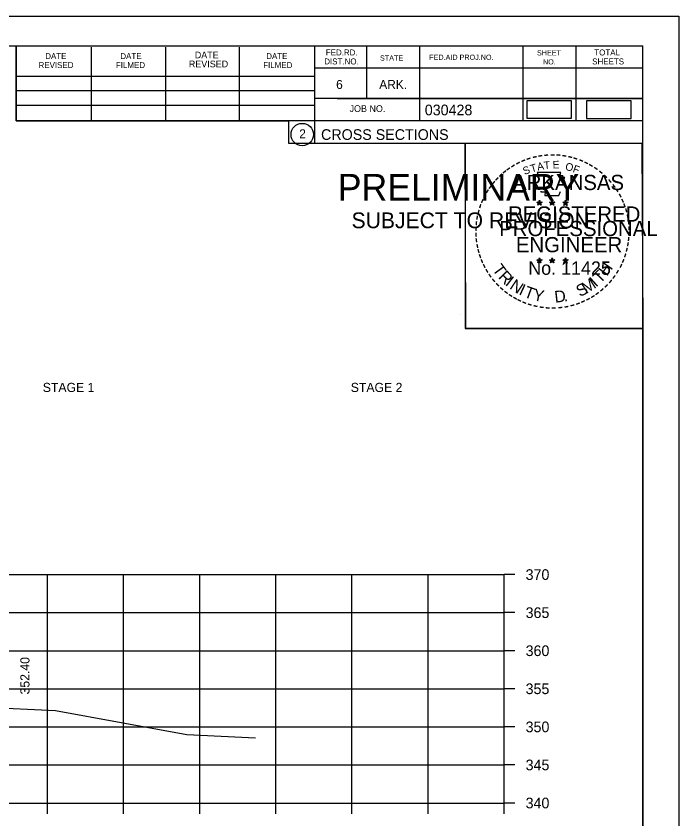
# Model space of a CAD drawing. Extents: x 1374859 to 1376773, y 382242 to 389804.
# Drawn here: x 1376210.5 to 1376297.5, y 382563 to 382668.4 of the extents above; entities that cross this region are included whole.
import ezdxf

# ---------------------------------------------------------------- set-up
doc = ezdxf.new("R2010")
doc.units = 0
for name, color, linetype in [('R_Axis', 7, 'Continuous'), ('R_Axis Annot', 7, 'Continuous'), ('R_Border', 7, 'Continuous'), ('R_Border PE', 7, 'Continuous'), ('R_Border Prem', 7, 'Continuous'), ('R_Exist Surface', 7, 'Continuous'), ('R_Grid', 7, 'Continuous'), ('R_MOT', 7, 'Continuous'), ('R_No Plot', 7, 'Continuous'), ('R_Xsect Elev', 7, 'Continuous')]:
    doc.layers.add(name, color=color, linetype=linetype)

msp = doc.modelspace()

# ---------------------------------------------------------------- linework, layer by layer
at = {"layer": 'R_Axis'}
for p, q in [((1376274.57, 382565.06), (1376274.57, 382595.06)), ((1376275.97, 382595.06), (1376274.57, 382595.06)), ((1376275.97, 382590.06), (1376274.57, 382590.06)), ((1376275.97, 382585.06), (1376274.57, 382585.06)), ((1376275.97, 382580.06), (1376274.57, 382580.06)), ((1376275.97, 382575.06), (1376274.57, 382575.06)), ((1376275.97, 382570.06), (1376274.57, 382570.06)), ((1375994.57, 382565.06), (1376274.57, 382565.06)), ((1376214.57, 382563.66), (1376214.57, 382565.06)), ((1376224.57, 382563.66), (1376224.57, 382565.06)), ((1376234.57, 382563.66), (1376234.57, 382565.06)), ((1376244.57, 382563.66), (1376244.57, 382565.06)), ((1376254.57, 382563.66), (1376254.57, 382565.06)), ((1376264.57, 382563.66), (1376264.57, 382565.06)), ((1376274.57, 382563.66), (1376274.57, 382565.06)), ((1376275.97, 382565.06), (1376274.57, 382565.06))]:
    msp.add_line(p, q, dxfattribs=at)
at = {"layer": 'R_Border'}
for p, q in [((1375976.57, 382664.52), (1376292.75, 382664.52)), ((1376210.49, 382654.64), (1376210.49, 382664.52)), ((1376249.65, 382664.52), (1376249.65, 382651.72)), ((1376256.49, 382664.52), (1376256.49, 382657.58)), ((1376263.43, 382664.52), (1376263.43, 382654.64)), ((1376277.01, 382664.52), (1376277.01, 382654.64)), ((1376283.95, 382664.52), (1376283.95, 382654.64)), ((1376292.75, 382459.06), (1376292.75, 382664.52)), ((1376220.35, 382654.64), (1376220.35, 382664.32)), ((1376230.11, 382654.64), (1376230.11, 382664.32)), ((1376239.79, 382654.64), (1376239.79, 382664.32)), ((1376292.75, 382661.58), (1376249.65, 382661.58)), ((1376292.75, 382661.6), (1376292.75, 382661.6)), ((1376210.49, 382660.5), (1376249.65, 382660.5)), ((1376210.49, 382658.64), (1376249.65, 382658.64)), ((1376292.75, 382657.58), (1376249.65, 382657.58)), ((1376252.61, 382657.58), (1376292.75, 382657.58)), ((1376210.49, 382654.64), (1376210.49, 382656.7)), ((1376210.49, 382656.7), (1376249.65, 382656.7)), ((1376292.75, 382654.64), (1376210.49, 382654.64)), ((1376249.65, 382651.72), (1376292.75, 382651.72))]:
    msp.add_line(p, q, dxfattribs=at)
msp.add_circle((1376248.04, 382652.85), 1.47, dxfattribs=at)
at = {"layer": 'R_Border PE'}
for p, q in [((1376278.84, 382643.97), (1376279.18, 382643.86)), ((1376278.84, 382643.97), (1376279.09, 382643.93)), ((1376278.84, 382643.97), (1376279.07, 382643.85)), ((1376278.97, 382643.57), (1376279.18, 382643.86)), ((1376278.97, 382643.57), (1376279.09, 382643.81)), ((1376278.97, 382643.57), (1376279.18, 382643.78)), ((1376279.18, 382644.23), (1376279.14, 382643.98)), ((1376279.18, 382643.86), (1376279.18, 382644.23)), ((1376279.18, 382644.23), (1376279.23, 382643.98)), ((1376279.53, 382643.97), (1376279.18, 382643.86)), ((1376279.4, 382643.57), (1376279.18, 382643.86)), ((1376279.4, 382643.57), (1376279.18, 382643.78)), ((1376279.53, 382643.97), (1376279.25, 382643.92)), ((1376279.4, 382643.57), (1376279.26, 382643.86)), ((1376279.53, 382643.97), (1376279.33, 382643.87)), ((1376280.51, 382643.97), (1376280.85, 382643.86)), ((1376280.51, 382643.97), (1376280.76, 382643.93)), ((1376280.51, 382643.97), (1376280.74, 382643.85)), ((1376280.64, 382643.57), (1376280.85, 382643.86)), ((1376280.64, 382643.57), (1376280.76, 382643.81)), ((1376280.64, 382643.57), (1376280.85, 382643.78)), ((1376280.85, 382644.23), (1376280.81, 382643.98)), ((1376280.85, 382643.86), (1376280.85, 382644.23)), ((1376280.85, 382644.23), (1376280.9, 382643.98)), ((1376281.2, 382643.97), (1376280.85, 382643.86)), ((1376281.07, 382643.57), (1376280.85, 382643.86)), ((1376281.07, 382643.57), (1376280.85, 382643.78)), ((1376281.2, 382643.97), (1376280.92, 382643.92)), ((1376281.07, 382643.57), (1376280.93, 382643.86)), ((1376281.2, 382643.97), (1376281, 382643.87)), ((1376282.27, 382643.96), (1376282.62, 382643.85)), ((1376282.27, 382643.96), (1376282.52, 382643.92)), ((1376282.27, 382643.96), (1376282.51, 382643.84)), ((1376282.4, 382643.55), (1376282.62, 382643.85)), ((1376282.4, 382643.55), (1376282.53, 382643.8)), ((1376282.4, 382643.55), (1376282.62, 382643.77)), ((1376282.62, 382644.22), (1376282.58, 382643.96)), ((1376282.62, 382643.85), (1376282.62, 382644.22)), ((1376282.62, 382644.22), (1376282.67, 382643.97)), ((1376282.97, 382643.96), (1376282.62, 382643.85)), ((1376282.83, 382643.55), (1376282.62, 382643.85)), ((1376282.83, 382643.55), (1376282.62, 382643.77)), ((1376282.97, 382643.96), (1376282.68, 382643.91)), ((1376282.83, 382643.55), (1376282.69, 382643.84)), ((1376282.97, 382643.96), (1376282.76, 382643.86)), ((1376278.83, 382636.4), (1376279.18, 382636.29)), ((1376278.83, 382636.4), (1376279.08, 382636.36)), ((1376278.83, 382636.4), (1376279.07, 382636.28)), ((1376278.96, 382635.99), (1376279.18, 382636.29)), ((1376278.96, 382635.99), (1376279.09, 382636.24)), ((1376278.96, 382635.99), (1376279.18, 382636.21)), ((1376279.18, 382636.65), (1376279.14, 382636.4)), ((1376279.18, 382636.29), (1376279.18, 382636.65)), ((1376279.18, 382636.65), (1376279.23, 382636.4)), ((1376279.53, 382636.4), (1376279.18, 382636.29)), ((1376279.39, 382635.99), (1376279.18, 382636.29)), ((1376279.39, 382635.99), (1376279.18, 382636.21)), ((1376279.53, 382636.4), (1376279.24, 382636.35)), ((1376279.39, 382635.99), (1376279.26, 382636.28)), ((1376279.53, 382636.4), (1376279.32, 382636.3)), ((1376280.5, 382636.4), (1376280.85, 382636.29)), ((1376280.5, 382636.4), (1376280.75, 382636.36)), ((1376280.5, 382636.4), (1376280.74, 382636.28)), ((1376280.63, 382635.99), (1376280.85, 382636.29)), ((1376280.63, 382635.99), (1376280.76, 382636.24)), ((1376280.63, 382635.99), (1376280.85, 382636.21)), ((1376280.85, 382636.65), (1376280.81, 382636.4)), ((1376280.85, 382636.29), (1376280.85, 382636.65)), ((1376280.85, 382636.65), (1376280.9, 382636.4)), ((1376281.2, 382636.4), (1376280.85, 382636.29)), ((1376281.06, 382635.99), (1376280.85, 382636.29)), ((1376281.06, 382635.99), (1376280.85, 382636.21)), ((1376281.2, 382636.4), (1376280.91, 382636.35)), ((1376281.06, 382635.99), (1376280.93, 382636.28)), ((1376281.2, 382636.4), (1376280.99, 382636.3)), ((1376282.27, 382636.39), (1376282.62, 382636.28)), ((1376282.27, 382636.39), (1376282.52, 382636.35)), ((1376282.27, 382636.39), (1376282.5, 382636.27)), ((1376282.4, 382635.98), (1376282.62, 382636.28)), ((1376282.4, 382635.98), (1376282.53, 382636.23)), ((1376282.4, 382635.98), (1376282.61, 382636.2)), ((1376282.62, 382636.64), (1376282.58, 382636.39)), ((1376282.83, 382635.98), (1376282.61, 382636.2)), ((1376282.62, 382636.28), (1376282.62, 382636.64)), ((1376282.62, 382636.64), (1376282.67, 382636.39)), ((1376282.96, 382636.39), (1376282.62, 382636.28)), ((1376282.83, 382635.98), (1376282.62, 382636.28)), ((1376282.96, 382636.39), (1376282.68, 382636.34)), ((1376282.83, 382635.98), (1376282.69, 382636.27)), ((1376282.96, 382636.39), (1376282.76, 382636.29))]:
    msp.add_line(p, q, dxfattribs=at)
for points in [[(1376278.88, 382647.85), (1376279.15, 382647.02)], [(1376282.39, 382646.93), (1376282.53, 382647.21), (1376281.84, 382647.19), (1376281.99, 382647.85), (1376278.88, 382647.85)], [(1376279.37, 382645.43), (1376279.37, 382645.34), (1376279.93, 382645.32), (1376279.88, 382644.85), (1376281.75, 382644.85), (1376281.95, 382645.39)], [(1376279.18, 382644.23), (1376279.4, 382643.57), (1376278.84, 382643.97), (1376279.53, 382643.97), (1376278.97, 382643.57), (1376279.18, 382644.23)], [(1376280.85, 382644.23), (1376281.07, 382643.57), (1376280.51, 382643.97), (1376281.2, 382643.97), (1376280.64, 382643.57), (1376280.85, 382644.23)], [(1376282.62, 382644.22), (1376282.83, 382643.55), (1376282.27, 382643.96), (1376282.97, 382643.96), (1376282.4, 382643.55), (1376282.62, 382644.22)], [(1376279.18, 382636.65), (1376279.39, 382635.99), (1376278.83, 382636.4), (1376279.53, 382636.4), (1376278.96, 382635.99), (1376279.18, 382636.65)], [(1376280.85, 382636.65), (1376281.06, 382635.99), (1376280.5, 382636.4), (1376281.2, 382636.4), (1376280.63, 382635.99), (1376280.85, 382636.65)], [(1376282.62, 382636.64), (1376282.83, 382635.98), (1376282.27, 382636.39), (1376282.96, 382636.39), (1376282.4, 382635.98), (1376282.62, 382636.64)]]:
    msp.add_lwpolyline(points, dxfattribs=at)
for centre, radius in [((1376279.18, 382643.86), 0.172), ((1376279.18, 382643.86), 0.145), ((1376279.18, 382643.86), 0.116), ((1376279.18, 382643.86), 0.0991), ((1376279.18, 382643.86), 0.0747), ((1376279.18, 382643.86), 0.0495), ((1376279.18, 382643.86), 0.0296), ((1376280.85, 382643.86), 0.172), ((1376280.85, 382643.86), 0.145), ((1376280.85, 382643.86), 0.116), ((1376280.85, 382643.86), 0.0991), ((1376280.85, 382643.86), 0.0747), ((1376280.85, 382643.86), 0.0495), ((1376280.85, 382643.86), 0.0296), ((1376282.62, 382643.85), 0.172), ((1376282.62, 382643.85), 0.145), ((1376282.62, 382643.85), 0.116), ((1376282.62, 382643.85), 0.0991), ((1376282.62, 382643.85), 0.0747), ((1376282.62, 382643.85), 0.0495), ((1376282.62, 382643.85), 0.0296), ((1376279.18, 382636.29), 0.172), ((1376279.18, 382636.29), 0.145), ((1376279.18, 382636.29), 0.116), ((1376279.18, 382636.29), 0.0991), ((1376279.18, 382636.29), 0.0747), ((1376279.18, 382636.29), 0.0495), ((1376279.18, 382636.29), 0.0296), ((1376280.85, 382636.29), 0.172), ((1376280.85, 382636.29), 0.145), ((1376280.85, 382636.29), 0.116), ((1376280.85, 382636.29), 0.0991), ((1376280.85, 382636.29), 0.0747), ((1376280.85, 382636.29), 0.0495), ((1376280.85, 382636.29), 0.0296), ((1376282.62, 382636.28), 0.172), ((1376282.62, 382636.28), 0.145), ((1376282.62, 382636.28), 0.116), ((1376282.62, 382636.28), 0.0991), ((1376282.62, 382636.28), 0.0747), ((1376282.62, 382636.28), 0.0495), ((1376282.62, 382636.28), 0.0296)]:
    msp.add_circle(centre, radius, dxfattribs=at)
at = {"layer": 'R_Exist Surface'}
msp.add_lwpolyline([(1376060.43, 382576.48), (1376068.34, 382576.55), (1376071, 382576.59), (1376082.43, 382577.26), (1376101.6, 382577.35), (1376109.94, 382581.24), (1376116.08, 382584.23), (1376119.45, 382584.36), (1376124.3, 382584.58), (1376129.36, 382584.71), (1376136.25, 382584.9), (1376143.14, 382584.76), (1376148.34, 382584.64), (1376153.09, 382584.37), (1376159.76, 382583.99), (1376162.71, 382583.21), (1376183.39, 382577.86), (1376192.2, 382577.96), (1376195.38, 382577.66), (1376206.34, 382577.64), (1376215.62, 382577.22), (1376232.89, 382574.07), (1376241.89, 382573.61)], dxfattribs=at)
at = {"layer": 'R_Grid'}
for p, q in [((1375994.57, 382595.06), (1376274.57, 382595.06)), ((1376214.57, 382565.06), (1376214.57, 382595.06)), ((1376224.57, 382565.06), (1376224.57, 382595.06)), ((1376234.57, 382565.06), (1376234.57, 382595.06)), ((1376244.57, 382565.06), (1376244.57, 382595.06)), ((1376254.57, 382565.06), (1376254.57, 382595.06)), ((1376264.57, 382565.06), (1376264.57, 382595.06)), ((1376274.57, 382565.06), (1376274.57, 382595.06)), ((1375994.57, 382590.06), (1376274.57, 382590.06)), ((1375994.57, 382585.06), (1376274.57, 382585.06)), ((1375994.57, 382580.06), (1376274.57, 382580.06)), ((1375994.57, 382575.06), (1376274.57, 382575.06)), ((1375994.57, 382570.06), (1376274.57, 382570.06)), ((1375994.57, 382565.06), (1376274.57, 382565.06))]:
    msp.add_line(p, q, dxfattribs=at)
at = {"layer": 'R_MOT'}
for points in [[(1376277.55, 382654.99), (1376283.38, 382654.99), (1376283.38, 382657.3), (1376277.55, 382657.3)], [(1376285.38, 382654.98), (1376291.21, 382654.98), (1376291.21, 382657.29), (1376285.38, 382657.29)]]:
    msp.add_lwpolyline(points, close=True, dxfattribs=at)
at = {"layer": 'R_No Plot'}
for p, q in [((1375964.17, 382668.41), (1376297.5, 382668.41)), ((1376268.78, 382629.26), (1376268.78, 382629.26))]:
    msp.add_line(p, q, dxfattribs=at)
for points in [[(1375964.16, 382668.41), (1376297.5, 382668.41), (1376297.5, 382455.08), (1375964.16, 382455.08)], [(1376210.49, 382664.52), (1376210.49, 382654.64), (1376246.22, 382654.64), (1376246.22, 382651.72), (1376269.42, 382651.72), (1376269.42, 382627.39), (1376292.75, 382627.39), (1376292.75, 382459.06), (1375976.57, 382459.06), (1375976.57, 382664.52)], [(1376269.42, 382651.72), (1376292.63, 382651.72), (1376292.75, 382627.39), (1376269.54, 382627.39)]]:
    msp.add_lwpolyline(points, close=True, dxfattribs=at)

# ---------------------------------------------------------------- texts
at = {"layer": 'R_Axis Annot'}
for s, p in [('STAGE 1', (1376213.97, 382619.04)), ('STAGE 2', (1376254.41, 382619.04))]:
    msp.add_text(s, height=1.2, rotation=360, dxfattribs=at).set_placement(p)
for s, p in [('370', (1376277.37, 382594.36)), ('365', (1376277.37, 382589.36)), ('360', (1376277.37, 382584.36)), ('355', (1376277.37, 382579.36)), ('350', (1376277.37, 382574.36)), ('345', (1376277.37, 382569.36)), ('340', (1376277.37, 382564.36))]:
    msp.add_text(s, height=1.4, dxfattribs=at).set_placement(p)
at = {"layer": 'R_Border'}
for s, height, p in [('DATE', 0.782, (1376214.29, 382662.76)), ('DATE', 0.782, (1376224.15, 382662.76)), ('DATE', 0.879, (1376233.93, 382662.86)), ('DATE', 0.782, (1376243.31, 382662.76)), ('FED.RD.', 0.782, (1376251.13, 382663.24)), ('SHEET', 0.684, (1376278.87, 382663.24)), ('TOTAL', 0.782, (1376286.39, 382663.24)), ('REVISED', 0.782, (1376213.41, 382661.58)), ('REVISED', 0.879, (1376233.15, 382661.68)), ('DIST.NO.', 0.782, (1376250.93, 382662.06)), ('STATE', 0.684, (1376258.25, 382662.56)), ('FED.AID PROJ.NO.', 0.684, (1376264.71, 382662.66)), ('NO.', 0.684, (1376279.65, 382662.06)), ('SHEETS', 0.782, (1376286.11, 382662.06)), ('FILMED', 0.782, (1376223.57, 382661.58)), ('FILMED', 0.782, (1376242.91, 382661.58)), ('6', 1.17, (1376252.49, 382658.84)), ('ARK.', 1.172, (1376258.15, 382658.84)), ('JOB NO.', 0.879, (1376254.25, 382655.82)), ('030428', 1.4, (1376264.13, 382655.38)), ('2', 1.17, (1376247.65, 382652.37)), ('CROSS SECTIONS', 1.4, (1376250.51, 382652.15))]:
    msp.add_text(s, height=height, rotation=360, dxfattribs=at).set_placement(p)
at = {"layer": 'R_Border PE'}
for s, height, rotation, p in [('-', 1.6, 19.1761, (1376277.62, 382648.98)), ('-', 1.6, 13.6301, (1376278.37, 382649.22)), ('-', 1.6, 10.2193, (1376279.05, 382649.38)), ('-', 1.6, 5.8968, (1376279.78, 382649.49)), ('-', 1.6, 0.1862, (1376280.55, 382649.56)), ('-', 1.6, 357.743, (1376281.28, 382649.55)), ('-', 1.6, 352.1617, (1376282.02, 382649.49)), ('-', 1.6, 347.2049, (1376282.74, 382649.38)), ('-', 1.6, 342.3362, (1376283.37, 382649.23)), ('-', 1.6, 34.0636, (1376275.76, 382648.02)), ('-', 1.6, 28.7918, (1376276.36, 382648.39)), ('-', 1.6, 24.3072, (1376276.99, 382648.71)), ('S', 1, 21.594, (1376277.23, 382647.53)), ('T', 1, 16.4036, (1376278.15, 382647.86)), ('A', 1, 11.2132, (1376278.97, 382648.11)), ('T', 1, 6.0228, (1376279.82, 382648.28)), ('E', 1, 0.8323, (1376280.93, 382648.39)), ('O', 1, 350.4515, (1376282.53, 382648.18)), ('F', 1, 340.0707, (1376283.48, 382647.95)), ('-', 1.6, 337.8551, (1376284.11, 382649)), ('-', 1.6, 334.1211, (1376284.74, 382648.73)), ('-', 1.6, 329.6409, (1376285.32, 382648.45)), ('-', 1.6, 42.9622, (1376274.27, 382646.83)), ('-', 1.6, 38.9507, (1376274.71, 382647.25)), ('-', 1.6, 36.2317, (1376275.18, 382647.63)), ('-', 1.6, 325.8627, (1376285.96, 382648.09)), ('-', 1.6, 320.5297, (1376286.57, 382647.66)), ('-', 1.6, 315.5786, (1376287.17, 382647.17)), ('-', 1.6, 50.6142, (1376273.42, 382645.87)), ('-', 1.6, 48.423, (1376273.83, 382646.35)), ('ARKANSAS', 2, 360, (1376275.73, 382645.56)), ('-', 1.6, 309.8797, (1376287.74, 382646.62)), ('-', 1.6, 58.0706, (1376272.68, 382644.77)), ('-', 1.6, 54.2325, (1376273.01, 382645.3)), ('-', 1.6, 306.6522, (1376288.27, 382646.02)), ('-', 1.4, 303.6753, (1376288.75, 382645.45)), ('-', 1.6, 62.8713, (1376272.37, 382644.16)), ('-', 1.6, 299.6684, (1376289.07, 382644.85)), ('-', 1.6, 294.6628, (1376289.39, 382644.23)), ('-', 1.6, 72.3945, (1376271.89, 382642.92)), ('-', 1.6, 67.7743, (1376272.11, 382643.55)), ('REGISTERED', 2, 360, (1376275.05, 382641.41)), ('DWB', 0.01, 360, (1376279.17, 382643.86)), ('DWB', 0.01, 360, (1376280.84, 382643.86)), ('DWB', 0.01, 360, (1376282.61, 382643.85)), ('-', 1.6, 290.5728, (1376289.65, 382643.66)), ('-', 1.6, 75.461, (1376271.7, 382642.21)), ('-', 1.6, 285.1233, (1376289.89, 382643.08)), ('-', 1.6, 280.5493, (1376290.09, 382642.34)), ('-', 1.6, 85.1863, (1376271.49, 382640.8)), ('-', 1.6, 81.2013, (1376271.56, 382641.49)), ('PROFESSIONAL', 2, 360, (1376273.9, 382639.51)), ('-', 1.6, 276.5962, (1376290.25, 382641.57)), ('-', 1.6, 89.0622, (1376271.46, 382640.1)), ('-', 1.6, 274.3301, (1376290.31, 382640.85)), ('-', 1.6, 94.1959, (1376271.5, 382639.38)), ('-', 1.6, 98.9479, (1376271.57, 382638.71)), ('ENGINEER', 2, 360, (1376276.09, 382637.39)), ('-', 1.6, 263.5172, (1376290.32, 382639.55)), ('-', 1.6, 269.9407, (1376290.34, 382640.21)), ('-', 1.6, 101.7149, (1376271.71, 382637.98)), ('-', 1.6, 260.9953, (1376290.25, 382638.89)), ('-', 1.6, 105.4578, (1376271.87, 382637.38)), ('-', 1.6, 109.0874, (1376272.08, 382636.75)), ('-', 1.6, 252.8681, (1376289.96, 382637.5)), ('-', 1.6, 255.7626, (1376290.14, 382638.22)), ('-', 1.6, 114.0643, (1376272.34, 382636.15)), ('No. 11425', 1.757, 360, (1376277.72, 382634.43)), ('DWB', 0.01, 360, (1376279.17, 382636.28)), ('DWB', 0.01, 360, (1376280.84, 382636.28)), ('DWB', 0.01, 360, (1376282.6, 382636.27)), ('H', 1.54, 54.6088, (1376288.06, 382634.16)), ('-', 1.6, 247.8887, (1376289.74, 382636.82)), ('-', 1.6, 115.7289, (1376272.64, 382635.54)), ('-', 1.6, 120.4471, (1376273, 382634.95)), ('T', 1.54, 306.0406, (1376272.94, 382635.13)), ('R', 1.54, 314.005, (1376273.7, 382634.08)), ('T', 1.54, 46.6444, (1376287.17, 382633.22)), ('-', 1.6, 239.0712, (1376289.08, 382635.44)), ('-', 1.6, 244.6197, (1376289.48, 382636.19)), ('-', 1.6, 125.8934, (1376273.4, 382634.39)), ('-', 1.6, 130.7181, (1376273.86, 382633.84)), ('I', 1.54, 321.9694, (1376274.6, 382633.15)), ('M', 1.54, 32.6563, (1376285.32, 382631.89)), ('I', 1.54, 42.1136, (1376286.61, 382632.74)), ('-', 1.6, 233.8452, (1376288.68, 382634.79)), ('-', 1.6, 134.2238, (1376274.38, 382633.29)), ('N', 1.54, 326.5002, (1376275.17, 382632.68)), ('I', 1.54, 335.3603, (1376276.38, 382631.89)), ('T', 1.54, 339.8912, (1376277.04, 382631.56)), ('S', 1.54, 26.9312, (1376284.49, 382631.49)), ('-', 1.6, 225.7653, (1376287.77, 382633.66)), ('-', 1.6, 231.2538, (1376288.25, 382634.22)), ('-', 1.6, 138.9338, (1376274.91, 382632.83)), ('-', 1.6, 144.6463, (1376275.46, 382632.42)), ('-', 1.6, 148.0898, (1376276.02, 382632.05)), ('Y', 1.54, 347.8556, (1376278.26, 382631.12)), ('D', 1.54, 6.3969, (1376281.24, 382630.76)), ('-', 1.6, 212.2491, (1376286.17, 382632.29)), ('-', 1.6, 215.7363, (1376286.7, 382632.68)), ('-', 1.6, 221.0851, (1376287.25, 382633.15)), ('-', 1.6, 151.5704, (1376276.6, 382631.73)), ('-', 1.6, 154.6002, (1376277.12, 382631.48)), ('-', 1.6, 158.5612, (1376277.75, 382631.22)), ('.', 1.54, 13.7642, (1376282.43, 382630.89)), ('-', 1.6, 200.7184, (1376284.36, 382631.35)), ('-', 1.6, 204.2516, (1376284.98, 382631.63)), ('-', 1.6, 207.3568, (1376285.61, 382631.94)), ('-', 1.6, 162.7983, (1376278.43, 382631.01)), ('-', 1.6, 167.5555, (1376279.15, 382630.85)), ('-', 1.6, 173.1155, (1376279.92, 382630.74)), ('-', 1.6, 176.5183, (1376280.67, 382630.68)), ('-', 1.6, 181.5918, (1376281.41, 382630.7)), ('-', 1.6, 185.8167, (1376282.22, 382630.78)), ('-', 1.6, 191.2858, (1376282.96, 382630.91)), ('-', 1.6, 195.4743, (1376283.69, 382631.11))]:
    msp.add_text(s, height=height, rotation=rotation, dxfattribs=at).set_placement(p)
at = {"layer": 'R_Border Prem'}
for s, height, p in [('PRELIMINARY', 3.5, (1376252.7, 382644.18)), ('DWB', 0.01, (1376253.45, 382646.03)), ('SUBJECT TO REVISION', 2.0751, (1376254.51, 382640.55))]:
    msp.add_text(s, height=height, rotation=360, dxfattribs=at).set_placement(p)
at = {"layer": 'R_Xsect Elev'}
msp.add_text('352.40', height=1.2, rotation=90, dxfattribs=at).set_placement((1376212.22, 382579.32))

doc.saveas('drawing.dxf')
